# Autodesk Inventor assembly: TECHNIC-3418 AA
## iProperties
Created: 2008-01
Part Number: TECHNIC-3418 AA
Document SubType Name: Assembly
Designer: eruiz-tagle
Mass: 50.5766 g
Surface Area: 638.201 cm^2
Volume: 39.9723 cm^3
Density: 1.26529 g/cm^3
Author: eruiz-tagle
